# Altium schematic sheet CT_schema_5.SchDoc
size 422 x 246 mm
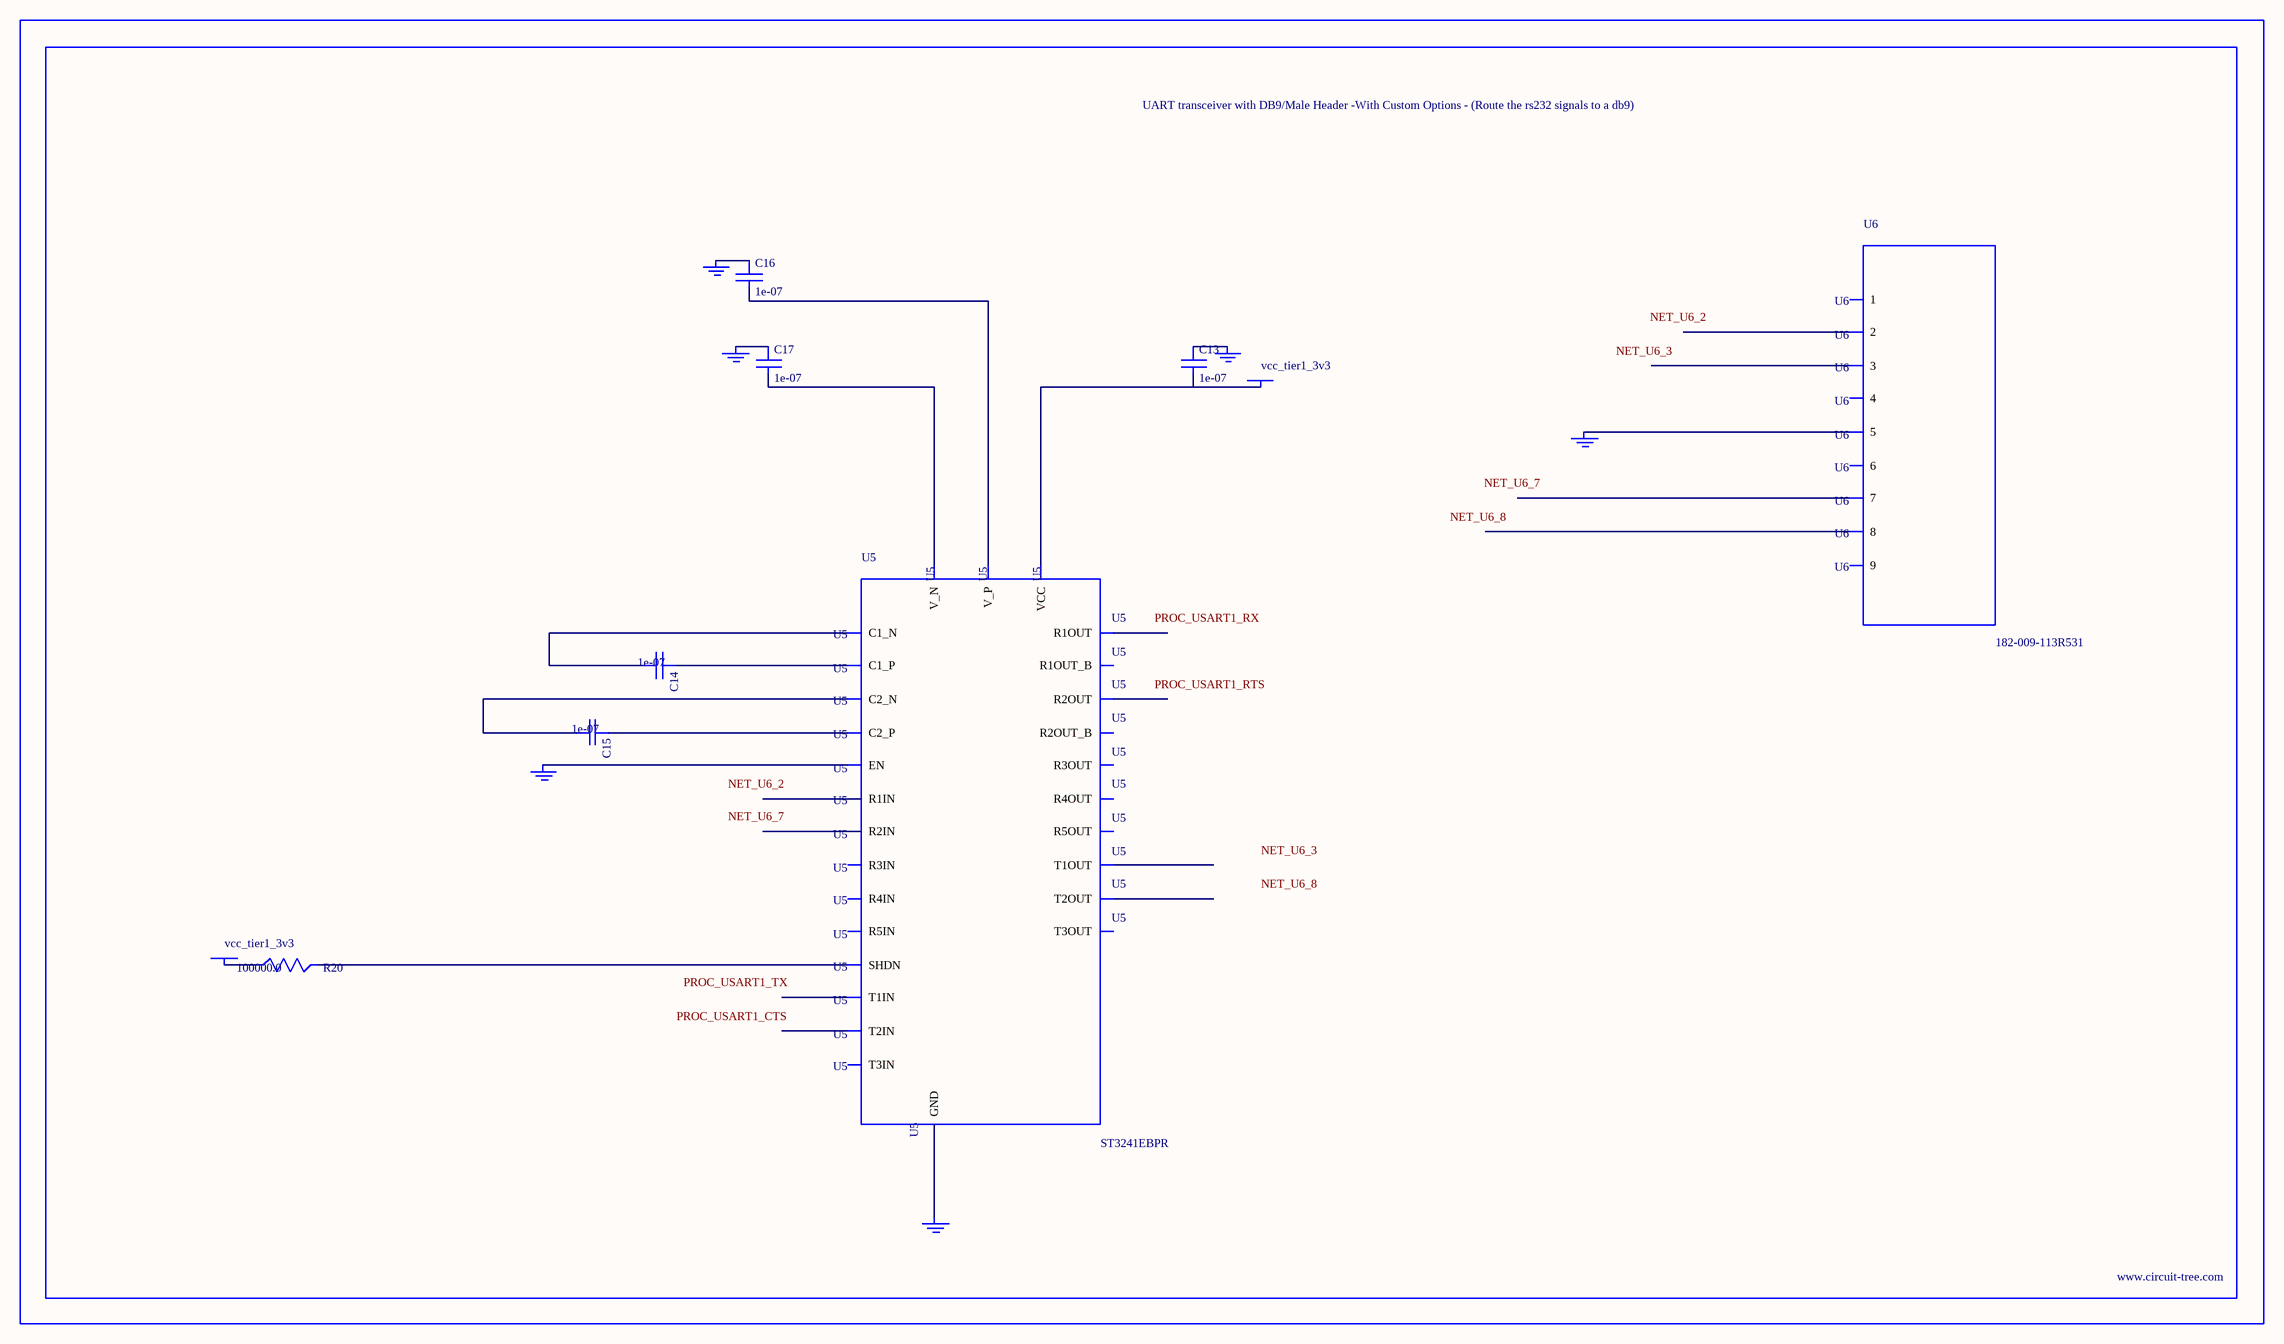
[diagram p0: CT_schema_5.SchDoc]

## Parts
BORDER4  (no value)
C13  1e-07  [C0402]
C14  1e-07  [C0402]
C15  1e-07  [C0402]
C16  1e-07  [C0402]
C17  1e-07  [C0402]
GND_INSTANCE_4_0  (no value)
GND_INSTANCE_4_1  (no value)
GND_INSTANCE_4_2  (no value)
GND_INSTANCE_4_3  (no value)
GND_INSTANCE_4_4  (no value)
GND_INSTANCE_4_5  (no value)
POWER_INSTANCE_4_0  vcc_tier1_3v3
POWER_INSTANCE_4_1  vcc_tier1_3v3
R20  100000.0  [R0603]
U5  ST3241EBPR  [SSOP-28]
U6  182-009-113R531  [182-009-MALE]

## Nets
NetC13_1: C13.1 GND_INSTANCE_4_2.0(GND)
NetC13_2: C13.2 POWER_INSTANCE_4_1.0(PWR) U5.26(VCC)
NetC14_1: C14.1 U5.28(C1_P)
NetC14_2: C14.2 U5.24(C1_N)
NetC15_1: C15.1 U5.1(C2_P)
NetC15_2: C15.2 U5.2(C2_N)
NetC16_1: C16.1 GND_INSTANCE_4_3.0(GND)
NetC16_2: C16.2 U5.27(V_P)
NetC17_1: C17.1 GND_INSTANCE_4_0.0(GND)
NetC17_2: C17.2 U5.3(V_N)
NetGND_INSTANCE_4_1_0: GND_INSTANCE_4_1.0(GND) U5.23(EN)
NetGND_INSTANCE_4_4_0: GND_INSTANCE_4_4.0(GND) U5.25(GND)
NetGND_INSTANCE_4_5_0: GND_INSTANCE_4_5.0(GND) U6.5
NetPOWER_INSTANCE_4_0_0: POWER_INSTANCE_4_0.0(PWR) R20.1
NetR20_2: R20.2 U5.22(SHDN)

Not connected (* = marked no-connect by the designer): U5 4(R1IN) 5(R2IN) 6(R3IN) 7(R4IN) 8(R5IN) 9(T1OUT) 10(T2OUT) 11(T3OUT) 12(T3IN) 13(T2IN) 14(T1IN) 15(R5OUT) 16(R4OUT) 17(R3OUT) 18(R2OUT) 19(R1OUT) 20(R2OUT_B) 21(R1OUT_B); U6 1 2 3 4 6 7 8 9

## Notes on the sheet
- Labels drawn without touching a wire or pin: NET_U6_2, NET_U6_3, NET_U6_7, NET_U6_8, PROC_USART1_CTS, PROC_USART1_RTS, PROC_USART1_RX, PROC_USART1_TX

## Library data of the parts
BORDER4 = BORDER_PAGE4
C13-C17 = C0402C104K3RACTU
GND_INSTANCE_4_0-GND_INSTANCE_4_5 = GND
POWER_INSTANCE_4_0 POWER_INSTANCE_4_1 = PWR
R20 = RC0603JR-07100KL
